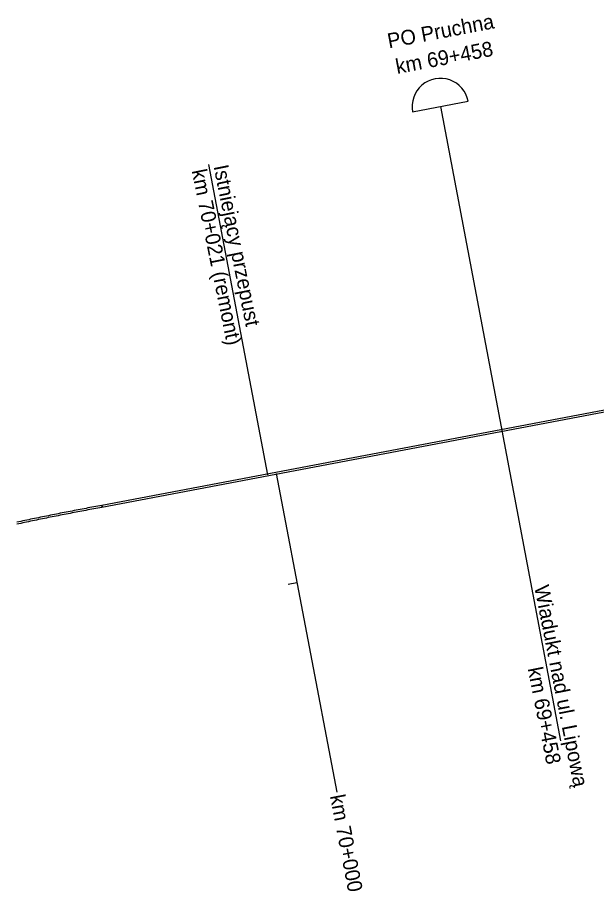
# Model space of a CAD drawing. Extents: x 6540402 to 6566579, y 5525343 to 5532423.
# Drawn here: x 6548635 to 6550002, y 5526135 to 5528197 of the extents above; entities that cross this region are included whole.
import ezdxf

# ---------------------------------------------------------------- set-up
doc = ezdxf.new("R2010")
doc.units = 0
for name, color, linetype in [('IR_ps_geometria', 7, 'Continuous'), ('TOR_PS_OPIS_T-hektometry projektowane', 7, 'Continuous'), ('TOR_PS_OPIS_T-opisy dodatkowe', 7, 'Continuous'), ('TOR_PS_OPIS_T-symbole geometrii', 7, 'Continuous'), ('TOR_PS_T-tory projektowane', 7, 'Continuous')]:
    doc.layers.add(name, color=color, linetype=linetype)

msp = doc.modelspace()

# ---------------------------------------------------------------- linework, layer by layer
at = {"layer": 'IR_ps_geometria'}
msp.add_lwpolyline([(6548834.3, 5527041.2), (6548834.4, 5527041), (6548834.4, 5527041), (6548834.4, 5527041), (6548834.5, 5527041), (6548834.5, 5527041), (6548834.5, 5527041), (6548834.6, 5527041), (6548834.6, 5527040.9), (6548834.6, 5527040.9), (6548834.6, 5527040.9), (6548834.7, 5527040.9), (6548834.7, 5527040.8), (6548834.7, 5527040.8), (6548834.7, 5527040.8), (6548834.7, 5527040.7), (6548834.7, 5527040.7), (6548834.7, 5527040.7), (6548834.7, 5527040.6), (6548834.6, 5527040.6), (6548834.6, 5527040.6), (6548834.6, 5527040.6), (6548834.6, 5527040.5), (6548834.5, 5527040.5), (6548834.5, 5527040.5), (6548834.5, 5527040.5), (6548834.4, 5527040.5), (6548834.4, 5527040.5), (6548834.4, 5527040.5), (6548834.3, 5527040.5), (6548834.3, 5527040.5), (6548834.3, 5527040.5), (6548834.3, 5527040.6), (6548834.2, 5527040.6), (6548834.2, 5527040.6), (6548834.2, 5527040.6), (6548834.2, 5527040.7), (6548834.2, 5527040.7), (6548834.2, 5527040.7), (6548834.2, 5527040.8), (6548834.2, 5527040.8), (6548834.2, 5527040.8), (6548834.2, 5527040.9), (6548834.2, 5527040.9), (6548834.2, 5527040.9), (6548834.3, 5527040.9), (6548834.3, 5527041), (6548834.3, 5527041), (6548834.4, 5527041), (6548834.4, 5527041), (6548834.3, 5527041.5), (6548834.3, 5527041.5), (6548834.2, 5527041.5), (6548834.2, 5527041.5), (6548834.2, 5527041.5), (6548834.1, 5527041.5), (6548834.1, 5527041.5), (6548834.1, 5527041.5), (6548834.1, 5527041.6), (6548834, 5527041.6), (6548834, 5527041.6), (6548834, 5527041.7), (6548834, 5527041.7), (6548834, 5527041.7), (6548834, 5527041.8), (6548834, 5527041.8), (6548834, 5527041.8), (6548834, 5527041.8), (6548834, 5527041.9), (6548834.1, 5527041.9), (6548834.1, 5527041.9), (6548834.1, 5527041.9), (6548834.1, 5527042), (6548834.2, 5527042), (6548834.2, 5527042), (6548834.2, 5527042), (6548834.3, 5527042), (6548834.3, 5527042), (6548834.3, 5527042), (6548834.4, 5527042), (6548834.4, 5527041.9), (6548834.4, 5527041.9), (6548834.4, 5527041.9), (6548834.5, 5527041.9), (6548834.5, 5527041.8), (6548834.5, 5527041.8), (6548834.5, 5527041.8), (6548834.5, 5527041.7), (6548834.5, 5527041.7), (6548834.5, 5527041.7), (6548834.5, 5527041.7), (6548834.5, 5527041.6), (6548834.4, 5527041.6), (6548834.4, 5527041.6), (6548834.4, 5527041.5), (6548834.4, 5527041.5), (6548834.4, 5527041.5), (6548834.3, 5527041.5), (6548834.3, 5527041.5)], close=True, dxfattribs=at)
msp.add_lwpolyline([(6548834.3, 5527041.2), (6548834.4, 5527041), (6548834.4, 5527041), (6548834.4, 5527041), (6548834.5, 5527041), (6548834.5, 5527041), (6548834.5, 5527041), (6548834.6, 5527041), (6548834.6, 5527040.9), (6548834.6, 5527040.9), (6548834.6, 5527040.9), (6548834.7, 5527040.9), (6548834.7, 5527040.8), (6548834.7, 5527040.8), (6548834.7, 5527040.8), (6548834.7, 5527040.7), (6548834.7, 5527040.7), (6548834.7, 5527040.7), (6548834.7, 5527040.6), (6548834.6, 5527040.6), (6548834.6, 5527040.6), (6548834.6, 5527040.6), (6548834.6, 5527040.5), (6548834.5, 5527040.5), (6548834.5, 5527040.5), (6548834.5, 5527040.5), (6548834.4, 5527040.5), (6548834.4, 5527040.5), (6548834.4, 5527040.5), (6548834.3, 5527040.5), (6548834.3, 5527040.5), (6548834.3, 5527040.5), (6548834.3, 5527040.6), (6548834.2, 5527040.6), (6548834.2, 5527040.6), (6548834.2, 5527040.6), (6548834.2, 5527040.7), (6548834.2, 5527040.7), (6548834.2, 5527040.7), (6548834.2, 5527040.8), (6548834.2, 5527040.8), (6548834.2, 5527040.8), (6548834.2, 5527040.9), (6548834.2, 5527040.9), (6548834.2, 5527040.9), (6548834.3, 5527040.9), (6548834.3, 5527041), (6548834.3, 5527041), (6548834.4, 5527041), (6548834.4, 5527041), (6548834.3, 5527041.5), (6548834.3, 5527041.5), (6548834.2, 5527041.5), (6548834.2, 5527041.5), (6548834.2, 5527041.5), (6548834.1, 5527041.5), (6548834.1, 5527041.5), (6548834.1, 5527041.5), (6548834.1, 5527041.6), (6548834, 5527041.6), (6548834, 5527041.6), (6548834, 5527041.7), (6548834, 5527041.7), (6548834, 5527041.7), (6548834, 5527041.8), (6548834, 5527041.8), (6548834, 5527041.8), (6548834, 5527041.8), (6548834, 5527041.9), (6548834.1, 5527041.9), (6548834.1, 5527041.9), (6548834.1, 5527041.9), (6548834.1, 5527042), (6548834.2, 5527042), (6548834.2, 5527042), (6548834.2, 5527042), (6548834.3, 5527042), (6548834.3, 5527042), (6548834.3, 5527042), (6548834.4, 5527042), (6548834.4, 5527041.9), (6548834.4, 5527041.9), (6548834.4, 5527041.9), (6548834.5, 5527041.9), (6548834.5, 5527041.8), (6548834.5, 5527041.8), (6548834.5, 5527041.8), (6548834.5, 5527041.7), (6548834.5, 5527041.7), (6548834.5, 5527041.7), (6548834.5, 5527041.7), (6548834.5, 5527041.6), (6548834.4, 5527041.6), (6548834.4, 5527041.6), (6548834.4, 5527041.5), (6548834.4, 5527041.5), (6548834.4, 5527041.5), (6548834.3, 5527041.5), (6548834.3, 5527041.5)], close=True, dxfattribs=at)
msp.add_lwpolyline([(6548834.3, 5527041.2), (6548834.4, 5527041), (6548834.4, 5527041), (6548834.4, 5527041), (6548834.5, 5527041), (6548834.5, 5527041), (6548834.5, 5527041), (6548834.6, 5527041), (6548834.6, 5527040.9), (6548834.6, 5527040.9), (6548834.6, 5527040.9), (6548834.7, 5527040.9), (6548834.7, 5527040.8), (6548834.7, 5527040.8), (6548834.7, 5527040.8), (6548834.7, 5527040.7), (6548834.7, 5527040.7), (6548834.7, 5527040.7), (6548834.7, 5527040.6), (6548834.6, 5527040.6), (6548834.6, 5527040.6), (6548834.6, 5527040.6), (6548834.6, 5527040.5), (6548834.5, 5527040.5), (6548834.5, 5527040.5), (6548834.5, 5527040.5), (6548834.4, 5527040.5), (6548834.4, 5527040.5), (6548834.4, 5527040.5), (6548834.3, 5527040.5), (6548834.3, 5527040.5), (6548834.3, 5527040.5), (6548834.3, 5527040.6), (6548834.2, 5527040.6), (6548834.2, 5527040.6), (6548834.2, 5527040.6), (6548834.2, 5527040.7), (6548834.2, 5527040.7), (6548834.2, 5527040.7), (6548834.2, 5527040.8), (6548834.2, 5527040.8), (6548834.2, 5527040.8), (6548834.2, 5527040.9), (6548834.2, 5527040.9), (6548834.2, 5527040.9), (6548834.3, 5527040.9), (6548834.3, 5527041), (6548834.3, 5527041), (6548834.4, 5527041), (6548834.4, 5527041), (6548834.3, 5527041.5), (6548834.3, 5527041.5), (6548834.2, 5527041.5), (6548834.2, 5527041.5), (6548834.2, 5527041.5), (6548834.1, 5527041.5), (6548834.1, 5527041.5), (6548834.1, 5527041.5), (6548834.1, 5527041.6), (6548834, 5527041.6), (6548834, 5527041.6), (6548834, 5527041.7), (6548834, 5527041.7), (6548834, 5527041.7), (6548834, 5527041.8), (6548834, 5527041.8), (6548834, 5527041.8), (6548834, 5527041.8), (6548834, 5527041.9), (6548834.1, 5527041.9), (6548834.1, 5527041.9), (6548834.1, 5527041.9), (6548834.1, 5527042), (6548834.2, 5527042), (6548834.2, 5527042), (6548834.2, 5527042), (6548834.3, 5527042), (6548834.3, 5527042), (6548834.3, 5527042), (6548834.4, 5527042), (6548834.4, 5527041.9), (6548834.4, 5527041.9), (6548834.4, 5527041.9), (6548834.5, 5527041.9), (6548834.5, 5527041.8), (6548834.5, 5527041.8), (6548834.5, 5527041.8), (6548834.5, 5527041.7), (6548834.5, 5527041.7), (6548834.5, 5527041.7), (6548834.5, 5527041.7), (6548834.5, 5527041.6), (6548834.4, 5527041.6), (6548834.4, 5527041.6), (6548834.4, 5527041.5), (6548834.4, 5527041.5), (6548834.4, 5527041.5), (6548834.3, 5527041.5), (6548834.3, 5527041.5)], close=True, dxfattribs=at)
msp.add_lwpolyline([(6548834.3, 5527041.2), (6548834.4, 5527041), (6548834.4, 5527041), (6548834.4, 5527041), (6548834.5, 5527041), (6548834.5, 5527041), (6548834.5, 5527041), (6548834.6, 5527041), (6548834.6, 5527040.9), (6548834.6, 5527040.9), (6548834.6, 5527040.9), (6548834.7, 5527040.9), (6548834.7, 5527040.8), (6548834.7, 5527040.8), (6548834.7, 5527040.8), (6548834.7, 5527040.7), (6548834.7, 5527040.7), (6548834.7, 5527040.7), (6548834.7, 5527040.6), (6548834.6, 5527040.6), (6548834.6, 5527040.6), (6548834.6, 5527040.6), (6548834.6, 5527040.5), (6548834.5, 5527040.5), (6548834.5, 5527040.5), (6548834.5, 5527040.5), (6548834.4, 5527040.5), (6548834.4, 5527040.5), (6548834.4, 5527040.5), (6548834.3, 5527040.5), (6548834.3, 5527040.5), (6548834.3, 5527040.5), (6548834.3, 5527040.6), (6548834.2, 5527040.6), (6548834.2, 5527040.6), (6548834.2, 5527040.6), (6548834.2, 5527040.7), (6548834.2, 5527040.7), (6548834.2, 5527040.7), (6548834.2, 5527040.8), (6548834.2, 5527040.8), (6548834.2, 5527040.8), (6548834.2, 5527040.9), (6548834.2, 5527040.9), (6548834.2, 5527040.9), (6548834.3, 5527040.9), (6548834.3, 5527041), (6548834.3, 5527041), (6548834.4, 5527041), (6548834.4, 5527041), (6548834.3, 5527041.5), (6548834.3, 5527041.5), (6548834.2, 5527041.5), (6548834.2, 5527041.5), (6548834.2, 5527041.5), (6548834.1, 5527041.5), (6548834.1, 5527041.5), (6548834.1, 5527041.5), (6548834.1, 5527041.6), (6548834, 5527041.6), (6548834, 5527041.6), (6548834, 5527041.7), (6548834, 5527041.7), (6548834, 5527041.7), (6548834, 5527041.8), (6548834, 5527041.8), (6548834, 5527041.8), (6548834, 5527041.8), (6548834, 5527041.9), (6548834.1, 5527041.9), (6548834.1, 5527041.9), (6548834.1, 5527041.9), (6548834.1, 5527042), (6548834.2, 5527042), (6548834.2, 5527042), (6548834.2, 5527042), (6548834.3, 5527042), (6548834.3, 5527042), (6548834.3, 5527042), (6548834.4, 5527042), (6548834.4, 5527041.9), (6548834.4, 5527041.9), (6548834.4, 5527041.9), (6548834.5, 5527041.9), (6548834.5, 5527041.8), (6548834.5, 5527041.8), (6548834.5, 5527041.8), (6548834.5, 5527041.7), (6548834.5, 5527041.7), (6548834.5, 5527041.7), (6548834.5, 5527041.7), (6548834.5, 5527041.6), (6548834.4, 5527041.6), (6548834.4, 5527041.6), (6548834.4, 5527041.5), (6548834.4, 5527041.5), (6548834.4, 5527041.5), (6548834.3, 5527041.5), (6548834.3, 5527041.5)], close=True, dxfattribs=at)
at = {"layer": 'TOR_PS_OPIS_T-hektometry projektowane'}
msp.add_lwpolyline([(6549245.8, 5527120.9), (6549388.9, 5526369.4)], dxfattribs=at)
at = {"layer": 'TOR_PS_OPIS_T-opisy dodatkowe'}
for p, q in [((6549568, 5527974.1), (6549699, 5527999)), ((6549086.5, 5527849.7), (6549225.2, 5527117.8)), ((6549778.2, 5527222.8), (6549917, 5526490.8)), ((6549294.9, 5526863), (6549274.3, 5526859.1))]:
    msp.add_line(p, q, dxfattribs=at)
msp.add_lwpolyline([(6549633.5, 5527986.5), (6549779, 5527218.8)], dxfattribs=at)
msp.add_arc((6549633.5, 5527986.5), 66.7, 10.7332, 190.7332, dxfattribs=at)
at = {"layer": 'TOR_PS_OPIS_T-symbole geometrii'}
for q in [(6548834.3, 5527044.9), (6548835.1, 5527042.9), (6548835.2, 5527045.1)]:
    msp.add_line((6548834.6, 5527045.9), q, dxfattribs=at)
at = {"layer": 'TOR_PS_T-tory projektowane'}
for p, q in [((6550320, 5527327.4), (6548834.6, 5527045.9)), ((6550239, 5527307.5), (6548834.3, 5527041.2))]:
    msp.add_line(p, q, dxfattribs=at)
for points in [[(6548834.3, 5527041.2), (6548829.7, 5527040.4), (6548825, 5527039.5), (6548820.3, 5527038.6), (6548815.7, 5527037.7), (6548811, 5527036.8), (6548806.3, 5527035.9), (6548801.6, 5527035), (6548797, 5527034.1), (6548792.3, 5527033.3), (6548787.6, 5527032.4), (6548783, 5527031.5), (6548778.3, 5527030.6), (6548773.6, 5527029.7), (6548769, 5527028.8), (6548764.3, 5527027.9), (6548759.6, 5527027), (6548755, 5527026.1), (6548750.3, 5527025.2), (6548745.6, 5527024.3), (6548741, 5527023.4), (6548736.3, 5527022.4), (6548731.6, 5527021.5), (6548727, 5527020.6), (6548722.3, 5527019.7), (6548717.6, 5527018.8), (6548713, 5527017.8), (6548708.3, 5527016.9), (6548703.6, 5527016), (6548699, 5527015), (6548694.3, 5527014.1), (6548689.7, 5527013.1), (6548685, 5527012.2), (6548680.3, 5527011.2), (6548675.7, 5527010.3), (6548671, 5527009.3), (6548666.4, 5527008.4), (6548661.7, 5527007.4), (6548657.1, 5527006.4), (6548652.4, 5527005.4), (6548647.8, 5527004.4), (6548643.1, 5527003.4), (6548638.5, 5527002.5), (6548633.8, 5527001.5)], [(6548834.6, 5527045.9), (6548829.9, 5527045), (6548825.2, 5527044.1), (6548820.6, 5527043.2), (6548815.9, 5527042.3), (6548811.2, 5527041.4), (6548806.6, 5527040.6), (6548801.9, 5527039.7), (6548797.2, 5527038.8), (6548792.6, 5527037.9), (6548787.9, 5527037), (6548783.2, 5527036.1), (6548778.5, 5527035.2), (6548773.9, 5527034.3), (6548769.2, 5527033.4), (6548764.5, 5527032.5), (6548759.9, 5527031.6), (6548755.2, 5527030.7), (6548750.5, 5527029.8), (6548745.9, 5527028.9), (6548741.2, 5527028), (6548736.5, 5527027.1), (6548731.9, 5527026.2), (6548727.2, 5527025.2), (6548722.5, 5527024.3), (6548717.9, 5527023.4), (6548713.2, 5527022.5), (6548708.6, 5527021.5), (6548703.9, 5527020.6), (6548699.2, 5527019.7), (6548694.6, 5527018.7), (6548689.9, 5527017.8), (6548685.3, 5527016.8), (6548680.6, 5527015.9), (6548675.9, 5527014.9), (6548671.3, 5527014), (6548666.6, 5527013), (6548662, 5527012), (6548657.3, 5527011), (6548652.7, 5527010.1), (6548648, 5527009.1), (6548643.4, 5527008.1), (6548638.7, 5527007.1), (6548634.1, 5527006.1)]]:
    msp.add_lwpolyline(points, dxfattribs=at)

# ---------------------------------------------------------------- texts
at = {"layer": 'TOR_PS_OPIS_T-hektometry projektowane'}
msp.add_text('km 70+000', height=35, rotation=280.7814, dxfattribs=at).set_placement((6549372.8, 5526360.4))
at = {"layer": 'TOR_PS_OPIS_T-opisy dodatkowe'}
for s, rotation, p in [('PO Pruchna', 10.7332, (6549512.1, 5528123.8)), ('km 69+458', 10.7332, (6549531.4, 5528063.4)), ('km 70+021 (remont)', 281.4331, (6549046.5, 5527835.3)), ('Istniejący przepust', 281.4331, (6549098, 5527845.7)), ('Wiadukt nad ul. Lipową', 281.1578, (6549854.9, 5526854)), ('km 69+458', 281.1578, (6549839.4, 5526661))]:
    msp.add_text(s, height=35, rotation=rotation, dxfattribs=at).set_placement(p)

doc.saveas('drawing.dxf')
